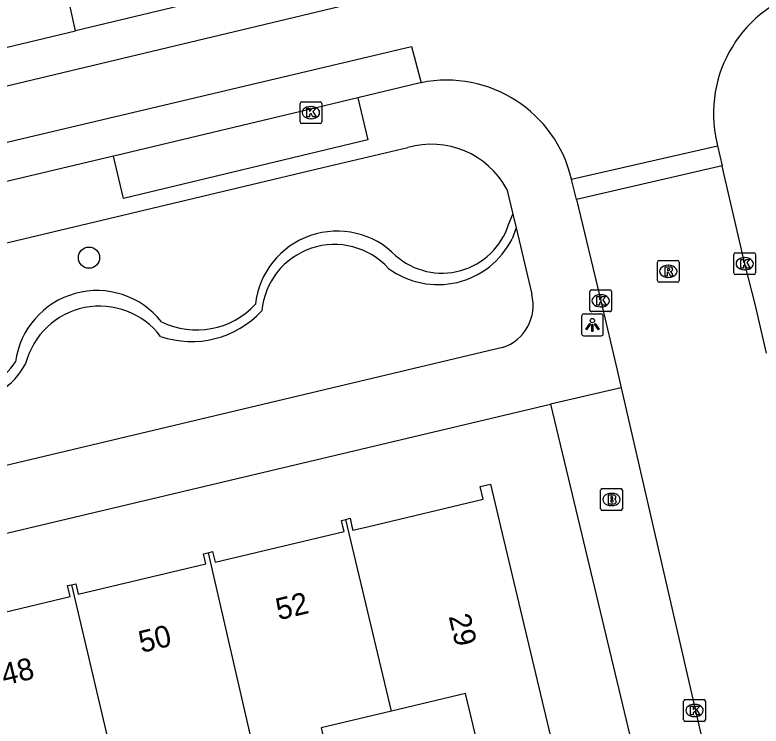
# Model space of a CAD drawing. Extents: x 162082 to 163393, y 388091 to 388632.
# Drawn here: x 163005.43 to 163039.74, y 388240.83 to 388273.52 of the extents above; entities that cross this region are included whole.
import ezdxf

# ---------------------------------------------------------------- set-up
doc = ezdxf.new("R2010")
doc.units = 0
for name, color, linetype in [('IMGEO_Boom', 7, 'Continuous'), ('IMGEO_Brandkraan', 7, 'Continuous'), ('IMGEO_Haag', 7, 'Continuous'), ('IMGEO_Kolk', 7, 'Continuous'), ('IMGEO_Lichtpunt', 7, 'Continuous'), ('IMGEO_Pand', 7, 'Continuous'), ('IMGEO_Pand_nummerreeks', 7, 'Continuous'), ('IMGEO_Rijbaan_lokaal_gesloten', 7, 'Continuous'), ('IMGEO_Rijbaan_lokaal_open', 7, 'Continuous'), ('IMGEO_Rioolput', 7, 'Continuous'), ('IMGEO_Voetpad_open', 7, 'Continuous')]:
    doc.layers.add(name, color=color, linetype=linetype)

msp = doc.modelspace()

# ---------------------------------------------------------------- linework, layer by layer
at = {"layer": 'IMGEO_Boom'}
msp.add_circle((163008.835, 388262.358), 0.489, dxfattribs=at)
at = {"layer": 'IMGEO_Brandkraan'}
for p, q in [((163032.363, 388250.815), (163032.363, 388251.667)), ((163032.438, 388251.741), (163033.29, 388251.741)), ((163032.851, 388251.521), (163032.876, 388251.521)), ((163033.364, 388251.667), (163033.364, 388250.815)), ((163032.874, 388250.961), (163032.849, 388250.961)), ((163033.29, 388250.741), (163032.438, 388250.741))]:
    msp.add_line(p, q, dxfattribs=at)
for points in [[(163032.363, 388250.815), (163032.363, 388251.667)], [(163032.438, 388251.741), (163033.29, 388251.741)], [(163033.364, 388251.667), (163033.364, 388250.815)], [(163032.711, 388251.441), (163032.711, 388251.041), (163032.924, 388251.041)], [(163032.942, 388251.441), (163032.711, 388251.441)], [(163032.89, 388251.36), (163032.836, 388251.36), (163032.836, 388251.284)], [(163032.836, 388251.284), (163032.889, 388251.284)], [(163032.898, 388251.208), (163032.836, 388251.208), (163032.836, 388251.127)], [(163032.836, 388251.127), (163032.898, 388251.127)], [(163033.29, 388250.741), (163032.438, 388250.741)]]:
    msp.add_lwpolyline(points, dxfattribs=at)
for centre, radius, start, end in [((163032.44, 388251.665), 0.0765, 91.552, 178.448), ((163032.44, 388251.665), 0.0765, 91.552, 178.448), ((163033.288, 388251.665), 0.0765, 1.552, 88.448), ((163033.288, 388251.665), 0.0765, 1.552, 88.448), ((163032.891, 388251.322), 0.0379, 267.8285, 90.9355), ((163032.899, 388251.167), 0.0404, 269.8759, 90.5077), ((163032.946, 388251.296), 0.145, 59.4692, 91.5367), ((163032.971, 388251.343), 0.0922, 285.5137, 58.1501), ((163032.976, 388251.151), 0.105, 301.3115, 78.989), ((163032.44, 388250.817), 0.0765, 181.552, 268.448), ((163032.44, 388250.817), 0.0765, 181.552, 268.448), ((163032.93, 388251.292), 0.251, 268.6676, 293.5347), ((163033.288, 388250.817), 0.0765, 271.552, 358.448), ((163033.288, 388250.817), 0.0765, 271.552, 358.448)]:
    msp.add_arc(centre, radius, start, end, dxfattribs=at)
for centre, major_axis, ratio, start_param, end_param in [((163032.85, 388251.241), (-0.387, 0.002), 0.722429, 4.712389, 7.853982), ((163032.875, 388251.241), (-0.39, 0.002), 0.717154, 1.570796, 4.712389)]:
    msp.add_ellipse(centre, major_axis=major_axis, ratio=ratio, start_param=start_param, end_param=end_param, dxfattribs=at)
at = {"layer": 'IMGEO_Haag'}
for points in [[(163028.131, 388263.881), (163028.322, 388264.364)], [(163028.472, 388263.727), (163028.29, 388263.215)]]:
    msp.add_lwpolyline(points, dxfattribs=at)
for centre, radius, start, end in [((163025.067, 388264.866), 3.218, 228.8688, 342.176), ((163020.248, 388259.79), 3.786, 44.468, 173.5942), ((163024.88, 388264.94), 3.822, 233.5981, 333.1696), ((163020.128, 388259.601), 3.36, 42.325, 174.7805), ((163009.203, 388257.064), 3.78, 38.4218, 172.2921), ((163009.325, 388256.617), 3.512, 37.106, 165.6631), ((163013.79, 388262.702), 3.669, 243.689, 317.2635), ((163013.547, 388262.924), 4.423, 251.2553, 316.9851), ((163002.878, 388259.128), 3.459, 217.0074, 331.6783), ((163002.946, 388259.209), 2.998, 214.3339, 326.8839)]:
    msp.add_arc(centre, radius, start, end, dxfattribs=at)
at = {"layer": 'IMGEO_Kolk'}
for p, q in [((163018.538, 388268.599), (163018.538, 388269.451)), ((163018.613, 388269.525), (163019.465, 388269.525)), ((163019.539, 388269.451), (163019.539, 388268.599)), ((163019.026, 388269.305), (163019.051, 388269.305)), ((163019.049, 388268.745), (163019.024, 388268.745)), ((163019.465, 388268.525), (163018.613, 388268.525)), ((163038.487, 388261.653), (163038.487, 388262.505)), ((163038.562, 388262.579), (163039.414, 388262.579)), ((163039.488, 388262.505), (163039.488, 388261.653)), ((163038.975, 388262.359), (163039, 388262.359)), ((163038.998, 388261.799), (163038.973, 388261.799)), ((163039.414, 388261.579), (163038.562, 388261.579)), ((163031.864, 388259.949), (163031.864, 388260.801)), ((163031.939, 388260.875), (163032.791, 388260.875)), ((163032.865, 388260.801), (163032.865, 388259.949)), ((163032.352, 388260.655), (163032.377, 388260.655)), ((163032.375, 388260.095), (163032.35, 388260.095)), ((163032.791, 388259.875), (163031.939, 388259.875)), ((163036.18, 388241.116), (163036.18, 388241.968)), ((163036.255, 388242.042), (163037.107, 388242.042)), ((163037.181, 388241.968), (163037.181, 388241.116)), ((163036.668, 388241.822), (163036.693, 388241.822)), ((163036.691, 388241.262), (163036.666, 388241.262)), ((163037.107, 388241.042), (163036.255, 388241.042))]:
    msp.add_line(p, q, dxfattribs=at)
for points in [[(163018.538, 388268.599), (163018.538, 388269.451)], [(163018.613, 388269.525), (163019.465, 388269.525)], [(163019.539, 388269.451), (163019.539, 388268.599)], [(163018.859, 388269.225), (163018.982, 388269.225), (163018.982, 388269.074), (163019.112, 388269.225), (163019.276, 388269.225), (163019.13, 388269.074), (163019.283, 388268.825), (163019.131, 388268.825), (163019.046, 388268.989), (163018.982, 388268.922), (163018.982, 388268.825), (163018.859, 388268.825), (163018.859, 388269.225)], [(163019.465, 388268.525), (163018.613, 388268.525)], [(163038.487, 388261.653), (163038.487, 388262.505)], [(163038.562, 388262.579), (163039.414, 388262.579)], [(163039.488, 388262.505), (163039.488, 388261.653)], [(163038.808, 388262.279), (163038.931, 388262.279), (163038.931, 388262.128), (163039.061, 388262.279), (163039.225, 388262.279), (163039.079, 388262.128), (163039.232, 388261.879), (163039.08, 388261.879), (163038.995, 388262.043), (163038.931, 388261.976), (163038.931, 388261.879), (163038.808, 388261.879), (163038.808, 388262.279)], [(163039.414, 388261.579), (163038.562, 388261.579)], [(163031.864, 388259.949), (163031.864, 388260.801)], [(163031.939, 388260.875), (163032.791, 388260.875)], [(163032.865, 388260.801), (163032.865, 388259.949)], [(163032.185, 388260.575), (163032.308, 388260.575), (163032.308, 388260.424), (163032.438, 388260.575), (163032.602, 388260.575), (163032.456, 388260.424), (163032.609, 388260.175), (163032.457, 388260.175), (163032.372, 388260.339), (163032.308, 388260.272), (163032.308, 388260.175), (163032.185, 388260.175), (163032.185, 388260.575)], [(163032.791, 388259.875), (163031.939, 388259.875)], [(163036.18, 388241.116), (163036.18, 388241.968)], [(163036.255, 388242.042), (163037.107, 388242.042)], [(163037.181, 388241.968), (163037.181, 388241.116)], [(163036.501, 388241.742), (163036.624, 388241.742), (163036.624, 388241.591), (163036.754, 388241.742), (163036.918, 388241.742), (163036.772, 388241.591), (163036.925, 388241.342), (163036.773, 388241.342), (163036.688, 388241.506), (163036.624, 388241.439), (163036.624, 388241.342), (163036.501, 388241.342), (163036.501, 388241.742)], [(163037.107, 388241.042), (163036.255, 388241.042)]]:
    msp.add_lwpolyline(points, dxfattribs=at)
for centre, start, end in [((163018.615, 388269.449), 91.552, 178.448), ((163018.615, 388269.449), 91.552, 178.448), ((163019.463, 388269.449), 1.552, 88.448), ((163019.463, 388269.449), 1.552, 88.448), ((163018.615, 388268.601), 181.552, 268.448), ((163018.615, 388268.601), 181.552, 268.448), ((163019.463, 388268.601), 271.552, 358.448), ((163019.463, 388268.601), 271.552, 358.448), ((163038.564, 388262.503), 91.552, 178.448), ((163038.564, 388262.503), 91.552, 178.448), ((163039.412, 388262.503), 1.552, 88.448), ((163039.412, 388262.503), 1.552, 88.448), ((163038.564, 388261.655), 181.552, 268.448), ((163038.564, 388261.655), 181.552, 268.448), ((163039.412, 388261.655), 271.552, 358.448), ((163039.412, 388261.655), 271.552, 358.448), ((163031.941, 388260.799), 91.552, 178.448), ((163031.941, 388260.799), 91.552, 178.448), ((163032.789, 388260.799), 1.552, 88.448), ((163032.789, 388260.799), 1.552, 88.448), ((163031.941, 388259.951), 181.552, 268.448), ((163031.941, 388259.951), 181.552, 268.448), ((163032.789, 388259.951), 271.552, 358.448), ((163032.789, 388259.951), 271.552, 358.448), ((163036.257, 388241.966), 91.552, 178.448), ((163036.257, 388241.966), 91.552, 178.448), ((163037.105, 388241.966), 1.552, 88.448), ((163037.105, 388241.966), 1.552, 88.448), ((163036.257, 388241.118), 181.552, 268.448), ((163036.257, 388241.118), 181.552, 268.448), ((163037.105, 388241.118), 271.552, 358.448), ((163037.105, 388241.118), 271.552, 358.448)]:
    msp.add_arc(centre, 0.0765, start, end, dxfattribs=at)
for centre, major_axis, ratio, start_param, end_param in [((163019.025, 388269.025), (-0.387, 0.002), 0.722429, 4.712389, 7.853982), ((163019.05, 388269.025), (-0.39, 0.002), 0.717154, 1.570796, 4.712389), ((163038.974, 388262.079), (-0.387, 0.002), 0.722429, 4.712389, 7.853982), ((163038.999, 388262.079), (-0.39, 0.002), 0.717154, 1.570796, 4.712389), ((163032.351, 388260.375), (-0.387, 0.002), 0.722429, 4.712389, 7.853982), ((163032.376, 388260.375), (-0.39, 0.002), 0.717154, 1.570796, 4.712389), ((163036.667, 388241.542), (-0.387, 0.002), 0.722429, 4.712389, 7.853982), ((163036.692, 388241.542), (-0.39, 0.002), 0.717154, 1.570796, 4.712389)]:
    msp.add_ellipse(centre, major_axis=major_axis, ratio=ratio, start_param=start_param, end_param=end_param, dxfattribs=at)
at = {"layer": 'IMGEO_Lichtpunt'}
for p, q in [((163032.389, 388259.762), (163031.581, 388259.762)), ((163032.389, 388259.762), (163031.581, 388259.762)), ((163031.487, 388259.667), (163031.487, 388258.86)), ((163031.487, 388259.667), (163031.487, 388258.86)), ((163032.483, 388258.86), (163032.483, 388259.667)), ((163032.483, 388258.86), (163032.483, 388259.667)), ((163031.581, 388258.766), (163032.389, 388258.766)), ((163031.581, 388258.766), (163032.389, 388258.766))]:
    msp.add_line(p, q, dxfattribs=at)
for points in [[(163031.861, 388259.331), (163031.9, 388259.303), (163031.712, 388259.041), (163031.674, 388259.068), (163031.861, 388259.331)], [(163031.963, 388259.283), (163032.01, 388259.283), (163032.01, 388258.961), (163031.963, 388258.961), (163031.963, 388259.283)], [(163032.073, 388259.303), (163032.111, 388259.33), (163032.298, 388259.068), (163032.259, 388259.04), (163032.073, 388259.303)]]:
    msp.add_lwpolyline(points, dxfattribs=at)
msp.add_circle((163031.986, 388259.465), 0.0994, dxfattribs=at)
for centre, start, end in [((163031.581, 388259.667), 90, 180), ((163031.581, 388259.667), 90, 180), ((163032.389, 388259.667), 0, 90), ((163032.389, 388259.667), 0, 90), ((163031.581, 388258.86), 180, 270), ((163031.581, 388258.86), 180, 270), ((163032.389, 388258.86), 270, 0), ((163032.389, 388258.86), 270, 360)]:
    msp.add_arc(centre, 0.0946, start, end, dxfattribs=at)
at = {"layer": 'IMGEO_Pand'}
for points in [[(163020.638, 388250.328), (163020.837, 388250.375), (163020.927, 388250), (163020.969, 388249.825), (163021.703, 388250), (163026.956, 388251.252), (163026.818, 388251.832), (163027.291, 388251.945), (163027.755, 388250), (163030.21, 388239.704), (163026.963, 388238.93), (163026.152, 388242.328), (163022.742, 388241.515)], [(163014.312, 388248.796), (163014.52, 388248.846), (163014.636, 388248.361), (163020.562, 388249.774), (163020.508, 388250), (163020.441, 388250.281), (163020.638, 388250.328)], [(163022.742, 388241.515), (163020.716, 388250), (163020.638, 388250.328)], [(163008.035, 388247.325), (163008.222, 388247.369), (163008.338, 388246.884), (163014.215, 388248.285), (163014.105, 388248.747), (163014.312, 388248.796)], [(163014.312, 388248.796), (163016.345, 388239.988)], [(163001.695, 388245.855), (163001.822, 388245.885), (163001.951, 388245.343), (163007.971, 388246.779), (163007.851, 388247.281), (163008.035, 388247.325)], [(163008.035, 388247.325), (163010.101, 388238.53)], [(163022.742, 388241.515), (163019.506, 388240.744), (163019.791, 388239.551), (163016.628, 388238.797), (163016.345, 388239.988)]]:
    msp.add_lwpolyline(points, dxfattribs=at)
at = {"layer": 'IMGEO_Rijbaan_lokaal_gesloten'}
for points in [[(163022.672, 388276.234), (163023.09, 388274.56), (162971.872, 388262.319), (162971.492, 388264.011)], [(163013.024, 388273.93), (163008.218, 388272.782)], [(162971.492, 388264.011), (163008.218, 388272.782)], [(162972.884, 388258.2), (162972.452, 388259.959), (163023.671, 388272.065), (163024.112, 388270.399)], [(163024.112, 388270.399), (163024.061, 388270.388), (163021.203, 388269.704)], [(163021.203, 388269.704), (163019.212, 388269.227), (163010.095, 388267.049), (163009.956, 388267.016)], [(163037.705, 388267.654), (163037.741, 388267.499)], [(163009.956, 388267.016), (162996.51, 388263.828)]]:
    msp.add_lwpolyline(points, dxfattribs=at)
for centre, radius, start, end in [((163043.417, 388268.987), 5.865, 103.787, 193.1346), ((163025.283, 388264.621), 5.895, 13.1372, 101.4561)]:
    msp.add_arc(centre, radius, start, end, dxfattribs=at)
at = {"layer": 'IMGEO_Rijbaan_lokaal_open'}
for points in [[(163031.024, 388265.961), (163037.741, 388267.499)], [(163037.741, 388267.499), (163037.952, 388266.575)], [(163037.952, 388266.575), (163031.248, 388265.028)], [(163039.991, 388257.973), (163039.484, 388260.157), (163038.988, 388262.079), (163038.045, 388266.167), (163037.952, 388266.575)], [(163031.248, 388265.028), (163031.039, 388265.894), (163031.024, 388265.961)], [(163031.248, 388265.028), (163032.365, 388260.375), (163033.118, 388257.186), (163033.304, 388256.379)], [(163033.304, 388256.379), (163038.037, 388235.809)]]:
    msp.add_lwpolyline(points, dxfattribs=at)
at = {"layer": 'IMGEO_Rioolput'}
for p, q in [((163034.972, 388261.301), (163034.972, 388262.153)), ((163035.047, 388262.227), (163035.899, 388262.227)), ((163035.973, 388262.153), (163035.973, 388261.301)), ((163035.46, 388262.007), (163035.485, 388262.007)), ((163035.899, 388261.227), (163035.047, 388261.227)), ((163035.483, 388261.447), (163035.458, 388261.447))]:
    msp.add_line(p, q, dxfattribs=at)
for points in [[(163034.972, 388261.301), (163034.972, 388262.153)], [(163035.047, 388262.227), (163035.899, 388262.227)], [(163035.973, 388262.153), (163035.973, 388261.301)], [(163035.561, 388261.925), (163035.309, 388261.927), (163035.309, 388261.527)], [(163035.487, 388261.846), (163035.433, 388261.846), (163035.433, 388261.765)], [(163035.309, 388261.527), (163035.433, 388261.527), (163035.433, 388261.689), (163035.444, 388261.689)], [(163035.433, 388261.765), (163035.485, 388261.765)], [(163035.491, 388261.66), (163035.562, 388261.527), (163035.702, 388261.527), (163035.637, 388261.653)], [(163035.899, 388261.227), (163035.047, 388261.227)]]:
    msp.add_lwpolyline(points, dxfattribs=at)
for centre, radius, start, end in [((163035.049, 388262.151), 0.0765, 91.552, 178.448), ((163035.049, 388262.151), 0.0765, 91.552, 178.448), ((163035.897, 388262.151), 0.0765, 1.552, 88.448), ((163035.897, 388262.151), 0.0765, 1.552, 88.448), ((163035.493, 388261.75), 0.0964, 77.0061, 93.1865), ((163035.507, 388261.807), 0.0378, 276.6634, 79.6772), ((163035.56, 388261.815), 0.109, 350.3612, 89.416), ((163035.558, 388261.815), 0.112, 277.5842, 350.9817), ((163035.443, 388261.636), 0.0533, 26.0293, 88.6989), ((163035.469, 388261.954), 0.19, 274.7715, 282.9687), ((163035.542, 388261.6), 0.108, 29.5134, 73.7905), ((163035.049, 388261.303), 0.0765, 181.552, 268.448), ((163035.049, 388261.303), 0.0765, 181.552, 268.448), ((163035.897, 388261.303), 0.0765, 271.552, 358.448), ((163035.897, 388261.303), 0.0765, 271.552, 358.448)]:
    msp.add_arc(centre, radius, start, end, dxfattribs=at)
for centre, major_axis, ratio, start_param, end_param in [((163035.459, 388261.727), (-0.387, 0.002), 0.722429, 4.712389, 7.853982), ((163035.484, 388261.727), (-0.39, 0.002), 0.717154, 1.570796, 4.712389)]:
    msp.add_ellipse(centre, major_axis=major_axis, ratio=ratio, start_param=start_param, end_param=end_param, dxfattribs=at)
at = {"layer": 'IMGEO_Voetpad_open'}
for points in [[(163008.218, 388272.782), (163007.922, 388274.103), (163012.723, 388275.265)], [(163021.203, 388269.704), (163021.663, 388267.767), (163010.417, 388265.07), (163009.956, 388267.016)], [(162986.413, 388255.159), (162985.767, 388257.851), (163001.699, 388261.631), (163001.557, 388262.213), (163019.583, 388266.507), (163023.493, 388267.421)], [(163028.047, 388265.513), (163028.322, 388264.364)], [(163028.322, 388264.364), (163028.472, 388263.727)], [(163028.472, 388263.727), (163029.195, 388260.675)], [(163027.856, 388258.227), (162989.812, 388249.184)], [(163033.304, 388256.379), (163030.055, 388255.625)], [(162988.107, 388245.667), (163000, 388248.495), (163006.344, 388250), (163030.055, 388255.625)], [(163030.055, 388255.625), (163031.402, 388250), (163035.741, 388231.88)]]:
    msp.add_lwpolyline(points, dxfattribs=at)
for centre, radius, start, end in [((163024.576, 388263.617), 3.955, 28.6459, 105.8894), ((163027.222, 388260.164), 2.038, 288.1172, 14.5275)]:
    msp.add_arc(centre, radius, start, end, dxfattribs=at)

# ---------------------------------------------------------------- texts
at = {"layer": 'IMGEO_Pand_nummerreeks'}
for s, rotation, p in [('52', 13.3923, (163017.556, 388245.686)), ('29', 283.4123, (163025.369, 388245.867)), ('50', 13.3923, (163011.249, 388244.185)), ('48', 13.3923, (163004.936, 388242.682))]:
    msp.add_text(s, height=1, rotation=rotation, dxfattribs=at).set_placement(p)

doc.saveas('drawing.dxf')
